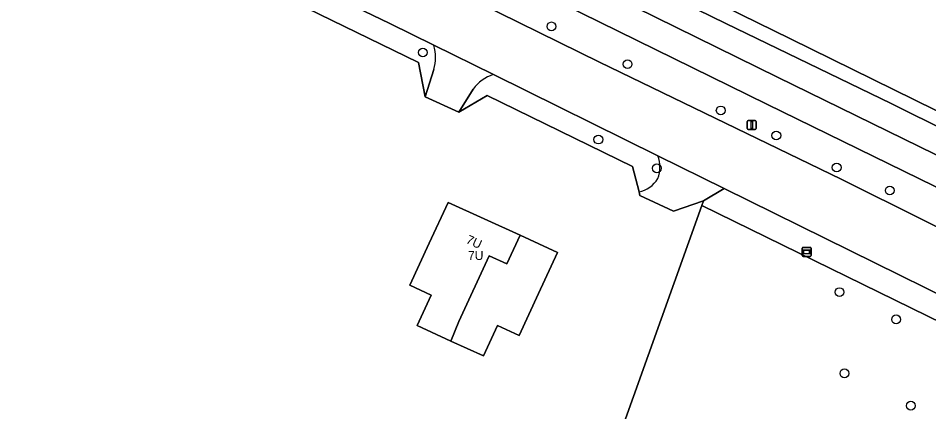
# Model space of a CAD drawing. Extents: x 156141 to 158132, y 385651 to 388333.
# Drawn here: x 156394 to 156494.8, y 386403.6 to 386447.2 of the extents above; entities that cross this region are included whole.
import ezdxf

# ---------------------------------------------------------------- set-up
doc = ezdxf.new("R2010")
doc.units = 0
for name, color, linetype in [('IMGEO_Berm_groen', 7, 'Continuous'), ('IMGEO_Boom', 7, 'Continuous'), ('IMGEO_Erf', 7, 'Continuous'), ('IMGEO_Fietspad_gesloten', 7, 'Continuous'), ('IMGEO_Grasland_overig', 7, 'Continuous'), ('IMGEO_Hek', 7, 'Continuous'), ('IMGEO_Lichtmast', 7, 'Continuous'), ('IMGEO_Loofbos', 7, 'Continuous'), ('IMGEO_Pand', 7, 'Continuous'), ('IMGEO_Pand_nummerreeks', 7, 'Continuous'), ('IMGEO_Rijbaan_lokaal_gesloten', 7, 'Continuous'), ('IMGEO_Verklikker', 7, 'Continuous'), ('IMGEO_Voetpad_open', 7, 'Continuous')]:
    doc.layers.add(name, color=color, linetype=linetype)

msp = doc.modelspace()

# ---------------------------------------------------------------- linework, layer by layer
at = {"layer": 'IMGEO_Berm_groen'}
for points in [[(156393.16, 386474.43), (156397.17, 386472.36), (156409.89, 386466.18), (156421.49, 386460.52), (156442.74, 386450.05), (156458.35, 386442.32), (156485.12, 386429.36), (156503.65, 386420.14), (156535.07, 386404.96), (156559.37, 386393.18), (156614.76, 386366.1), (156674.13, 386337.24)], [(156874.88, 386250), (156873.92, 386250.47), (156829.97, 386271.61), (156801.07, 386285.74), (156761.54, 386305.28), (156749.3, 386311.2), (156736.57, 386317.36), (156707.43, 386331.66), (156681.2, 386344.37), (156657.68, 386355.9), (156629.2, 386369.96), (156613.05, 386377.82), (156609.28, 386379.8), (156574.82, 386396.59), (156558.18, 386404.76), (156543.35, 386412.02), (156539.43, 386413.93), (156514.71, 386425.98), (156503.51, 386431.38), (156490.68, 386437.75), (156472.35, 386446.61), (156453.09, 386456.04), (156439.01, 386463.07)], [(156406.15, 386460.56), (156403.63, 386459.18), (156406.68, 386457.7), (156438.33, 386442.3), (156439.05, 386438.5), (156440.02, 386441.52)], [(156440.02, 386444.19), (156435.16, 386446.59), (156406.15, 386460.56)], [(156439.93, 386459.43), (156478.08, 386440.66), (156748.12, 386308.63), (156804.27, 386281.19), (156846.28, 386260.73), (156890.66, 386238.9), (156936.44, 386216.54), (157000.04, 386185.31), (157015.75, 386178.18)], [(157014.71, 386175.6), (157000, 386182.1), (156998.79, 386182.7), (156935.1, 386213.72), (156888.97, 386236.22), (156845.86, 386257.32), (156802.24, 386278.71), (156746.83, 386305.79), (156476.91, 386437.66), (156454.28, 386448.77), (156440.3, 386455.67)], [(156464.82, 386431.96), (156446.61, 386440.94)], [(156444.39, 386439.33), (156442.77, 386436.8), (156445.93, 386438.62), (156462.02, 386430.79), (156462.74, 386427.97)], [(156742.53, 386296.33), (156535.86, 386397.24), (156524.08, 386402.95), (156500, 386414.61), (156472.16, 386428.34), (156469.88, 386426.98), (156469.7, 386426.47), (156500, 386411.64), (156522.94, 386400.43), (156557.16, 386383.7), (156598.54, 386363.27), (156625.35, 386349.27)]]:
    msp.add_lwpolyline(points, dxfattribs=at)
for centre, radius, start, end in [((156434.97, 386442.85), 5.23, 345.2217, 14.7783), ((156447.84, 386436.91), 4.22, 107.0304, 144.9444), ((156461.55, 386430.68), 3.51, 339.4615, 21.4498), ((156462.08, 386431.13), 3.23, 281.6662, 328.5007)]:
    msp.add_arc(centre, radius, start, end, dxfattribs=at)
at = {"layer": 'IMGEO_Boom'}
for centre in [(156453.04, 386446.28), (156438.8, 386443.39), (156461.47, 386442.1), (156471.79, 386436.98), (156477.94, 386434.21), (156458.24, 386433.76), (156464.71, 386430.58), (156484.63, 386430.67), (156490.51, 386428.12), (156484.94, 386416.88), (156491.21, 386413.86), (156485.49, 386407.89), (156492.84, 386404.31)]:
    msp.add_circle(centre, 0.489, dxfattribs=at)
at = {"layer": 'IMGEO_Erf'}
msp.add_lwpolyline([(156460.68, 386401.29), (156469.7, 386426.47), (156469.88, 386426.98), (156466.54, 386425.84), (156462.84, 386427.57), (156462.74, 386427.97), (156462.02, 386430.79), (156445.93, 386438.62), (156442.77, 386436.8), (156439.05, 386438.5), (156438.33, 386442.3), (156406.68, 386457.7), (156403.63, 386459.18), (156400.28, 386457.34), (156396.7, 386459.72), (156397.15, 386461.17), (156396.34, 386461.57), (156396.55, 386462.74), (156387.03, 386467.37)], dxfattribs=at)
msp.add_lwpolyline([(156447.07, 386413.18), (156445.51, 386409.81), (156441.91, 386411.46), (156438.17, 386413.17), (156439.73, 386416.54), (156437.35, 386417.63), (156439.51, 386422.28), (156441.61, 386426.81), (156449.56, 386423.17), (156453.71, 386421.27), (156451.61, 386416.73), (156449.45, 386412.09)], close=True, dxfattribs=at)
at = {"layer": 'IMGEO_Fietspad_gesloten'}
msp.add_lwpolyline([(156440.3, 386455.67), (156454.28, 386448.77), (156476.91, 386437.66), (156746.83, 386305.79), (156748.12, 386308.63), (156478.08, 386440.66), (156439.93, 386459.43)], dxfattribs=at)
at = {"layer": 'IMGEO_Grasland_overig'}
msp.add_lwpolyline([(156625.35, 386349.27), (156598.54, 386363.27), (156557.16, 386383.7), (156522.94, 386400.43), (156500, 386411.64), (156469.7, 386426.47), (156460.68, 386401.29), (156460.2, 386400.06), (156462.63, 386399.06), (156486.95, 386387.02), (156509.11, 386375.43), (156519.92, 386370.3), (156531.52, 386364.75), (156542.93, 386359.58), (156550.14, 386355.98), (156559.71, 386351.24), (156570.36, 386346.01), (156583.4, 386339.46), (156593.06, 386334.88), (156606.62, 386328.01), (156628.11, 386317.67)], dxfattribs=at)
at = {"layer": 'IMGEO_Hek'}
for points in [[(156406.68, 386457.7), (156438.33, 386442.3), (156439.05, 386438.5)], [(156439.05, 386438.5), (156442.77, 386436.8)], [(156442.77, 386436.8), (156445.93, 386438.62), (156462.02, 386430.79), (156462.74, 386427.97)], [(156462.74, 386427.97), (156462.84, 386427.57), (156466.54, 386425.84), (156469.88, 386426.98)], [(156469.88, 386426.98), (156469.7, 386426.47)], [(156469.7, 386426.47), (156460.68, 386401.29)]]:
    msp.add_lwpolyline(points, dxfattribs=at)
at = {"layer": 'IMGEO_Lichtmast'}
for p, q in [((156474.73, 386434.97), (156474.73, 386435.77)), ((156474.73, 386435.77), (156474.73, 386434.97)), ((156474.83, 386435.87), (156475.62, 386435.87)), ((156475.62, 386435.87), (156474.83, 386435.87)), ((156475.72, 386435.77), (156475.72, 386434.97)), ((156475.72, 386434.97), (156475.72, 386435.77)), ((156475.62, 386434.87), (156474.83, 386434.87)), ((156474.83, 386434.87), (156475.62, 386434.87))]:
    msp.add_line(p, q, dxfattribs=at)
msp.add_lwpolyline([(156475.15, 386435.74), (156475.3, 386435.74), (156475.3, 386434.99), (156475.15, 386434.99), (156475.15, 386435.74)], dxfattribs=at)
for centre, start, end in [((156474.83, 386435.77), 90, 180), ((156474.83, 386435.77), 90, 180), ((156475.62, 386435.77), 0, 90), ((156475.62, 386435.77), 360, 90), ((156474.83, 386434.97), 180, 270), ((156474.83, 386434.97), 180, 270), ((156475.62, 386434.97), 270, 0), ((156475.62, 386434.97), 270, 0)]:
    msp.add_arc(centre, 0.1, start, end, dxfattribs=at)
at = {"layer": 'IMGEO_Loofbos'}
msp.add_lwpolyline([(156441.01, 386463.8), (156479.51, 386444.91), (156513.81, 386428.04), (156540.12, 386415.26), (156546.07, 386412.38), (156571.02, 386399.96), (156633.35, 386369.63), (156663.58, 386354.86), (156696.62, 386338.78), (156728.15, 386323.33), (156794.45, 386290.97), (156816.86, 386279.93), (156878.47, 386250), (156993.26, 386193.78), (156997.02, 386191.93), (156998.62, 386191.17), (157000, 386190.5)], dxfattribs=at)
at = {"layer": 'IMGEO_Pand'}
for points in [[(156449.56, 386423.17), (156441.61, 386426.81), (156439.51, 386422.28), (156437.35, 386417.63), (156439.73, 386416.54), (156438.17, 386413.17), (156441.91, 386411.46), (156442.79, 386413.62), (156446.15, 386420.89), (156448.1, 386419.99)], [(156449.56, 386423.17), (156448.1, 386419.99), (156446.15, 386420.89), (156442.79, 386413.62), (156441.91, 386411.46), (156445.51, 386409.81), (156447.07, 386413.18), (156449.45, 386412.09), (156451.61, 386416.73), (156453.71, 386421.27)]]:
    msp.add_lwpolyline(points, close=True, dxfattribs=at)
at = {"layer": 'IMGEO_Rijbaan_lokaal_gesloten'}
for points in [[(156384.44, 386478.89), (156361.03, 386490.15), (156354.65, 386493.26), (156351.59, 386494.77), (156350.23, 386495.44), (156343.25, 386490.3), (156361.06, 386482.03), (156382.33, 386471.61), (156394.82, 386466.1), (156398.15, 386464.42), (156406.15, 386460.56), (156435.16, 386446.59), (156440.02, 386444.19), (156446.61, 386440.94), (156464.82, 386431.96), (156472.16, 386428.34), (156500, 386414.61), (156524.08, 386402.95), (156535.86, 386397.24), (156742.53, 386296.33)], [(156535.07, 386404.96), (156503.65, 386420.14), (156485.12, 386429.36), (156458.35, 386442.32), (156442.74, 386450.05), (156421.49, 386460.52), (156409.89, 386466.18), (156397.17, 386472.36), (156393.16, 386474.43)], [(156446.61, 386440.94), (156440.02, 386444.19)], [(156440.02, 386441.52), (156439.05, 386438.5), (156442.77, 386436.8), (156444.39, 386439.33)], [(156462.74, 386427.97), (156462.84, 386427.57), (156466.54, 386425.84), (156469.88, 386426.98), (156472.16, 386428.34), (156464.82, 386431.96)]]:
    msp.add_lwpolyline(points, dxfattribs=at)
for centre, radius, start, end in [((156434.97, 386442.85), 5.23, 345.2217, 14.7783), ((156447.84, 386436.91), 4.22, 107.0304, 144.9444), ((156461.55, 386430.68), 3.51, 339.4615, 21.4498), ((156462.08, 386431.13), 3.23, 281.6662, 328.5007)]:
    msp.add_arc(centre, radius, start, end, dxfattribs=at)
at = {"layer": 'IMGEO_Verklikker'}
for p, q in [((156480.8, 386420.93), (156480.8, 386421.73)), ((156480.8, 386421.73), (156480.8, 386420.93)), ((156480.9, 386421.83), (156481.69, 386421.83)), ((156481.69, 386421.83), (156480.9, 386421.83)), ((156481.79, 386421.73), (156481.79, 386420.93)), ((156481.79, 386420.93), (156481.79, 386421.73)), ((156481.69, 386420.83), (156480.9, 386420.83)), ((156480.9, 386420.83), (156481.69, 386420.83))]:
    msp.add_line(p, q, dxfattribs=at)
for points in [[(156480.91, 386421.56), (156481.69, 386421.56), (156481.69, 386421.1), (156480.91, 386421.1), (156480.91, 386421.56)], [(156480.97, 386421.5), (156480.97, 386421.16), (156481.63, 386421.16), (156481.63, 386421.5), (156480.97, 386421.5)]]:
    msp.add_lwpolyline(points, dxfattribs=at)
for centre, start, end in [((156480.9, 386421.73), 90, 180), ((156480.9, 386421.73), 90, 180), ((156481.69, 386421.73), 0, 90), ((156481.69, 386421.73), 360, 90), ((156480.9, 386420.93), 180, 270), ((156480.9, 386420.93), 180, 270), ((156481.69, 386420.93), 270, 0), ((156481.69, 386420.93), 270, 0)]:
    msp.add_arc(centre, 0.1, start, end, dxfattribs=at)
at = {"layer": 'IMGEO_Voetpad_open'}
for points in [[(156439.01, 386463.07), (156453.09, 386456.04), (156472.35, 386446.61), (156490.68, 386437.75), (156503.51, 386431.38), (156514.71, 386425.98), (156539.43, 386413.93), (156543.35, 386412.02), (156558.18, 386404.76), (156574.82, 386396.59), (156609.28, 386379.8), (156613.05, 386377.82), (156629.2, 386369.96)], [(157000, 386190.5), (156998.62, 386191.17), (156997.02, 386191.93), (156993.26, 386193.78), (156878.47, 386250), (156816.86, 386279.93), (156794.45, 386290.97), (156728.15, 386323.33), (156696.62, 386338.78), (156663.58, 386354.86), (156633.35, 386369.63), (156571.02, 386399.96), (156546.07, 386412.38), (156540.12, 386415.26), (156513.81, 386428.04), (156479.51, 386444.91), (156441.01, 386463.8)]]:
    msp.add_lwpolyline(points, dxfattribs=at)

# ---------------------------------------------------------------- texts
at = {"layer": 'IMGEO_Pand_nummerreeks'}
msp.add_text('7U', height=1, rotation=335.3833, dxfattribs=at).set_placement((156443.49, 386422.34))
msp.add_text('7U', height=1, dxfattribs=at).set_placement((156443.8, 386420.43))

doc.saveas('drawing.dxf')
